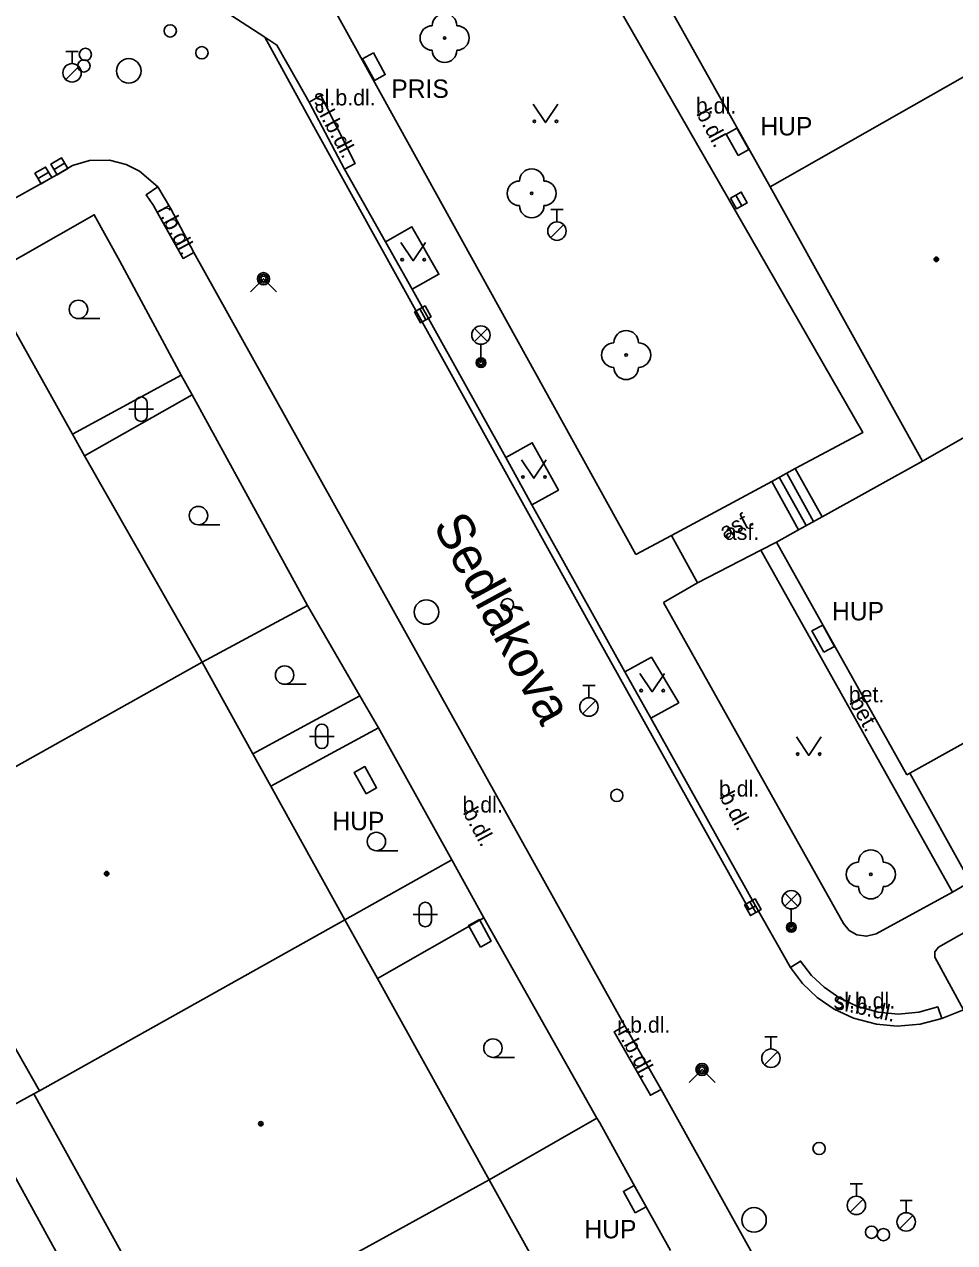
# Model space of a CAD drawing. Extents: x -600391 to -599491, y -1160176 to -1159402.
# Drawn here: x -600270.74 to -600232.82, y -1159878.4 to -1159828.77 of the extents above; entities that cross this region are included whole.
import ezdxf

# ---------------------------------------------------------------- set-up
doc = ezdxf.new("R2010")
doc.units = 0
for name, color, linetype in [('Level 10', 7, 'Continuous'), ('Level 11', 7, 'Continuous'), ('Level 22', 7, 'Continuous'), ('Level 24', 7, 'Continuous'), ('Level 27', 7, 'Continuous'), ('Level 28', 7, 'Continuous'), ('Level 31', 7, 'Continuous'), ('Level 33', 7, 'Continuous'), ('Level 36', 7, 'Continuous'), ('Level 39', 7, 'Continuous'), ('Level 40', 7, 'Continuous'), ('Level 41', 7, 'Continuous'), ('Level 5', 7, 'Continuous'), ('Level 50', 7, 'Continuous'), ('Level 51', 7, 'Continuous'), ('Level 7', 7, 'Continuous'), ('Level 8', 7, 'Continuous')]:
    doc.layers.add(name, color=color, linetype=linetype)

msp = doc.modelspace()

# ---------------------------------------------------------------- linework, layer by layer
at = {"layer": 'Level 10'}
for points in [[(-600266.56, -1159825.53), (-600265.79, -1159826.14), (-600260.94, -1159829.28)], [(-600260.94, -1159829.28), (-600260.44, -1159829.61), (-600259.6, -1159831.09), (-600259.13, -1159831.94)], [(-600259.13, -1159831.94), (-600257.69, -1159834.67)], [(-600269.41, -1159834.89), (-600268.78, -1159834.51), (-600268.08, -1159834.31), (-600267.27, -1159834.3), (-600266.59, -1159834.48), (-600266.04, -1159834.75), (-600265.3, -1159835.39)], [(-600368.24, -1159889.98), (-600352.5, -1159881.19), (-600321.09, -1159863.73), (-600299.81, -1159851.87), (-600276.88, -1159839.05), (-600269.41, -1159834.89)], [(-600257.69, -1159834.67), (-600256.02, -1159837.63)], [(-600263.83, -1159838.06), (-600264.78, -1159836.25), (-600265.3, -1159835.39)], [(-600246.27, -1159869.57), (-600263.83, -1159838.06)], [(-600256.02, -1159837.63), (-600254.93, -1159839.56)], [(-600254.93, -1159839.56), (-600251.12, -1159846.41)], [(-600251.12, -1159846.41), (-600250.05, -1159848.34)], [(-600250.05, -1159848.34), (-600246.26, -1159855.15)], [(-600246.26, -1159855.15), (-600245.2, -1159857.04)], [(-600245.2, -1159857.04), (-600240.94, -1159864.68)], [(-600240.94, -1159864.68), (-600239.52, -1159867.2)], [(-600233.34, -1159869.27), (-600234.23, -1159869.51), (-600235.17, -1159869.58), (-600236.01, -1159869.5), (-600236.94, -1159869.26), (-600237.74, -1159868.89), (-600238.43, -1159868.41), (-600239.02, -1159867.85), (-600239.52, -1159867.2)], [(-600233.34, -1159869.27), (-600232.46, -1159868.92)], [(-600244.78, -1159872.16), (-600246.27, -1159869.57)], [(-600220.17, -1159916.28), (-600233.36, -1159892.71), (-600244.78, -1159872.16)]]:
    msp.add_lwpolyline(points, dxfattribs=at)
at = {"layer": 'Level 11'}
for points in [[(-600239.32, -1159846.86), (-600236.57, -1159845.4), (-600252.37, -1159817.9)], [(-600240.94, -1159864.68), (-600241.2, -1159864.83), (-600247.35, -1159853.81), (-600254.65, -1159840.67), (-600258.86, -1159833.07), (-600260.94, -1159829.28)], [(-600257.69, -1159834.67), (-600257.25, -1159834.43), (-600258.65, -1159831.67), (-600259.13, -1159831.94)], [(-600263.83, -1159838.06), (-600264.27, -1159838.3), (-600265.24, -1159836.56), (-600265.47, -1159836.15), (-600265.77, -1159835.71), (-600265.3, -1159835.39)], [(-600256.02, -1159837.63), (-600254.94, -1159837.02), (-600253.84, -1159838.95), (-600254.93, -1159839.56)], [(-600268.78, -1159845.46), (-600264.34, -1159843.06)], [(-600268.28, -1159846.34), (-600263.89, -1159843.86)], [(-600251.12, -1159846.41), (-600250.04, -1159845.81), (-600248.97, -1159847.74), (-600250.05, -1159848.34)], [(-600240.28, -1159847.39), (-600239.32, -1159846.86)], [(-600239.32, -1159846.86), (-600238.23, -1159848.83)], [(-600244.36, -1159849.59), (-600240.28, -1159847.39)], [(-600240.28, -1159847.39), (-600239.19, -1159849.36)], [(-600239.97, -1159847.22), (-600238.88, -1159849.19)], [(-600239.67, -1159847.05), (-600238.57, -1159849.02)], [(-600245.82, -1159850.37), (-600244.36, -1159849.59)], [(-600244.36, -1159849.59), (-600243.31, -1159851.52)], [(-600240.72, -1159850.19), (-600240.09, -1159849.86)], [(-600243.31, -1159851.52), (-600240.72, -1159850.19)], [(-600232.91, -1159864.12), (-600240.72, -1159850.19)], [(-600244.69, -1159852.32), (-600243.31, -1159851.52)], [(-600244.69, -1159852.32), (-600237.35, -1159865.4)], [(-600246.26, -1159855.15), (-600245.18, -1159854.55), (-600244.07, -1159856.41), (-600245.2, -1159857.04)], [(-600261.42, -1159858.49), (-600257.06, -1159856.13)], [(-600260.69, -1159859.8), (-600256.31, -1159857.43)], [(-600232.91, -1159864.12), (-600232.19, -1159863.71)], [(-600237.35, -1159865.4), (-600237.12, -1159865.68), (-600236.81, -1159865.86), (-600236.41, -1159865.92), (-600236.02, -1159865.82), (-600232.91, -1159864.12)], [(-600232.46, -1159868.92), (-600233.63, -1159866.78), (-600233.63, -1159866.55), (-600233.48, -1159866.36), (-600230.72, -1159864.8)], [(-600256.34, -1159867.64), (-600252.01, -1159865.17)], [(-600239.52, -1159867.2), (-600239.1, -1159866.93), (-600238.66, -1159867.52), (-600238.14, -1159868), (-600237.51, -1159868.45), (-600236.81, -1159868.77), (-600235.94, -1159869.01), (-600235.12, -1159869.09), (-600234.28, -1159869.01), (-600233.51, -1159868.8), (-600233.34, -1159869.27)], [(-600246.27, -1159869.57), (-600246.7, -1159869.82), (-600245.22, -1159872.4), (-600244.78, -1159872.16)]]:
    msp.add_lwpolyline(points, dxfattribs=at)
at = {"layer": 'Level 22'}
for centre in [(-600253.61, -1159829.32), (-600250.06, -1159835.65), (-600246.21, -1159842.24), (-600236.24, -1159863.4)]:
    msp.add_circle(centre, 0.05, dxfattribs=at)
for centre, start, end in [((-600253.61, -1159828.82), 0, 180), ((-600254.11, -1159829.32), 90, 270), ((-600253.11, -1159829.32), 270, 90), ((-600253.61, -1159829.82), 180, 0), ((-600250.06, -1159835.15), 0, 180), ((-600250.56, -1159835.65), 90, 270), ((-600249.56, -1159835.65), 270, 90), ((-600250.06, -1159836.15), 180, 0), ((-600246.21, -1159841.74), 0, 180), ((-600246.71, -1159842.24), 90, 270), ((-600245.71, -1159842.24), 270, 90), ((-600246.21, -1159842.74), 180, 0), ((-600236.24, -1159862.9), 0, 180), ((-600236.74, -1159863.4), 90, 270), ((-600235.74, -1159863.4), 270, 90), ((-600236.24, -1159863.9), 180, 0)]:
    msp.add_arc(centre, 0.5, start, end, dxfattribs=at)
at = {"layer": 'Level 24'}
msp.add_lwpolyline([(-600256.949, -1159830.17), (-600256.471, -1159831.049), (-600256.031, -1159830.81), (-600256.509, -1159829.931)], close=True, dxfattribs=at)
for points in [[(-600241.65, -1159834.11), (-600242.14, -1159833.24), (-600241.7, -1159833), (-600241.21, -1159833.87), (-600241.65, -1159834.11)], [(-600238.15, -1159854.35), (-600238.64, -1159853.48), (-600238.2, -1159853.24), (-600237.72, -1159854.11), (-600238.15, -1159854.35)], [(-600256.81, -1159860.12), (-600257.3, -1159859.25), (-600256.86, -1159859.01), (-600256.38, -1159859.88), (-600256.81, -1159860.12)], [(-600252.15, -1159866.36), (-600252.63, -1159865.48), (-600252.19, -1159865.24), (-600251.71, -1159866.12), (-600252.15, -1159866.36)], [(-600245.84, -1159877.19), (-600246.32, -1159876.32), (-600245.88, -1159876.08), (-600245.4, -1159876.95), (-600245.84, -1159877.19)]]:
    msp.add_lwpolyline(points, dxfattribs=at)
at = {"layer": 'Level 27'}
for p, q in [((-600269.526, -1159834.676), (-600269.094, -1159834.424)), ((-600270.176, -1159835.046), (-600269.744, -1159834.794)), ((-600241.74, -1159835.721), (-600241.5, -1159836.159)), ((-600254.622, -1159840.362), (-600254.378, -1159840.798)), ((-600241.172, -1159864.522), (-600240.928, -1159864.958))]:
    msp.add_line(p, q, dxfattribs=at)
for points in [[(-600270.05, -1159835.262), (-600269.618, -1159835.01), (-600269.87, -1159834.578), (-600270.302, -1159834.83)], [(-600269.4, -1159834.892), (-600268.968, -1159834.64), (-600269.22, -1159834.208), (-600269.652, -1159834.46)], [(-600241.959, -1159835.841), (-600241.719, -1159836.279), (-600241.281, -1159836.039), (-600241.521, -1159835.601)], [(-600254.84, -1159840.483), (-600254.597, -1159840.92), (-600254.16, -1159840.677), (-600254.403, -1159840.24)], [(-600241.39, -1159864.643), (-600241.147, -1159865.08), (-600240.71, -1159864.837), (-600240.953, -1159864.4)]]:
    msp.add_lwpolyline(points, close=True, dxfattribs=at)
for centre in [(-600266.48, -1159830.66), (-600254.35, -1159852.71), (-600241, -1159877.48)]:
    msp.add_circle(centre, 0.5, dxfattribs=at)
at = {"layer": 'Level 28'}
for p, q in [((-600269.04, -1159829.865), (-600268.54, -1159829.865)), ((-600268.79, -1159830.365), (-600268.79, -1159829.865)), ((-600269.048, -1159831.012), (-600268.518, -1159830.482)), ((-600249.28, -1159836.315), (-600248.78, -1159836.315)), ((-600249.03, -1159836.815), (-600249.03, -1159836.315)), ((-600249.288, -1159837.462), (-600248.758, -1159836.932)), ((-600247.98, -1159855.705), (-600247.48, -1159855.705)), ((-600247.73, -1159856.205), (-600247.73, -1159855.705)), ((-600247.988, -1159856.852), (-600247.458, -1159856.322)), ((-600240.56, -1159870.015), (-600240.06, -1159870.015)), ((-600240.31, -1159870.515), (-600240.31, -1159870.015)), ((-600240.568, -1159871.162), (-600240.038, -1159870.632)), ((-600237.08, -1159876.015), (-600236.58, -1159876.015)), ((-600236.83, -1159876.515), (-600236.83, -1159876.015)), ((-600237.088, -1159877.162), (-600236.558, -1159876.632)), ((-600235.05, -1159876.685), (-600234.55, -1159876.685)), ((-600234.8, -1159877.185), (-600234.8, -1159876.685)), ((-600235.058, -1159877.832), (-600234.528, -1159877.302))]:
    msp.add_line(p, q, dxfattribs=at)
for centre, radius in [((-600264.79, -1159829.03), 0.25), ((-600268.25, -1159829.99), 0.25), ((-600263.5, -1159829.92), 0.25), ((-600268.79, -1159830.74), 0.375), ((-600268.31, -1159830.46), 0.25), ((-600249.03, -1159837.19), 0.375), ((-600251.05, -1159852.41), 0.25), ((-600247.73, -1159856.58), 0.375), ((-600246.59, -1159860.18), 0.25), ((-600240.31, -1159870.89), 0.375), ((-600238.35, -1159874.57), 0.25), ((-600236.83, -1159876.89), 0.375), ((-600234.8, -1159877.56), 0.375), ((-600236.21, -1159877.98), 0.25), ((-600235.73, -1159878.08), 0.25)]:
    msp.add_circle(centre, radius, dxfattribs=at)
at = {"layer": 'Level 31'}
for points in [[(-600261.52, -1159839.66), (-600260.99, -1159839.13), (-600260.46, -1159839.66)], [(-600243.65, -1159871.88), (-600243.12, -1159871.35), (-600242.59, -1159871.88)]]:
    msp.add_lwpolyline(points, dxfattribs=at)
for centre, radius in [((-600260.99, -1159839.13), 0.25), ((-600260.99, -1159839.13), 0.18), ((-600260.99, -1159839.13), 0.11), ((-600243.12, -1159871.35), 0.25), ((-600243.12, -1159871.35), 0.18), ((-600243.12, -1159871.35), 0.11)]:
    msp.add_circle(centre, radius, dxfattribs=at)
at = {"layer": 'Level 33'}
for p, q in [((-600252.395, -1159841.69), (-600251.865, -1159841.16)), ((-600252.395, -1159841.16), (-600251.865, -1159841.69)), ((-600252.13, -1159841.8), (-600252.13, -1159842.55)), ((-600239.745, -1159864.7), (-600239.215, -1159864.17)), ((-600239.745, -1159864.17), (-600239.215, -1159864.7)), ((-600239.48, -1159864.81), (-600239.48, -1159865.56))]:
    msp.add_line(p, q, dxfattribs=at)
for centre, radius in [((-600252.13, -1159841.425), 0.375), ((-600252.13, -1159842.55), 0.2), ((-600252.13, -1159842.55), 0.145), ((-600252.13, -1159842.55), 0.0876), ((-600239.48, -1159864.435), 0.375), ((-600239.48, -1159865.56), 0.2), ((-600239.48, -1159865.56), 0.145), ((-600239.48, -1159865.56), 0.0876)]:
    msp.add_circle(centre, radius, dxfattribs=at)
at = {"layer": 'Level 36'}
for p, q in [((-600268.53, -1159840.755), (-600267.655, -1159840.755)), ((-600266.476, -1159844.446), (-600265.476, -1159844.446)), ((-600266.226, -1159844.196), (-600266.226, -1159844.696)), ((-600265.726, -1159844.196), (-600265.726, -1159844.696)), ((-600263.64, -1159849.155), (-600262.765, -1159849.155)), ((-600260.13, -1159855.655), (-600259.255, -1159855.655)), ((-600259.116, -1159857.776), (-600258.116, -1159857.776)), ((-600258.866, -1159857.526), (-600258.866, -1159858.026)), ((-600258.366, -1159857.526), (-600258.366, -1159858.026)), ((-600256.39, -1159862.435), (-600255.515, -1159862.435)), ((-600254.646, -1159864.786), (-600254.646, -1159865.286)), ((-600254.146, -1159864.786), (-600254.146, -1159865.286)), ((-600254.896, -1159865.036), (-600253.896, -1159865.036)), ((-600251.64, -1159870.855), (-600250.765, -1159870.855))]:
    msp.add_line(p, q, dxfattribs=at)
for points in [[(-600250, -1159832.02), (-600249.5, -1159832.77), (-600249, -1159832.02)], [(-600255.39, -1159837.65), (-600254.89, -1159838.4), (-600254.39, -1159837.65)], [(-600250.47, -1159846.51), (-600249.97, -1159847.26), (-600249.47, -1159846.51)], [(-600245.65, -1159855.21), (-600245.15, -1159855.96), (-600244.65, -1159855.21)], [(-600239.27, -1159857.8), (-600238.77, -1159858.55), (-600238.27, -1159857.8)]]:
    msp.add_lwpolyline(points, dxfattribs=at)
for centre, radius in [((-600249.95, -1159832.72), 0.05), ((-600249.051, -1159832.72), 0.05), ((-600255.34, -1159838.35), 0.05), ((-600254.441, -1159838.35), 0.05), ((-600268.53, -1159840.38), 0.375), ((-600250.42, -1159847.21), 0.05), ((-600249.521, -1159847.21), 0.05), ((-600263.64, -1159848.78), 0.375), ((-600260.13, -1159855.28), 0.375), ((-600245.6, -1159855.91), 0.05), ((-600244.701, -1159855.91), 0.05), ((-600239.22, -1159858.5), 0.05), ((-600238.321, -1159858.5), 0.05), ((-600256.39, -1159862.06), 0.375), ((-600251.64, -1159870.48), 0.375)]:
    msp.add_circle(centre, radius, dxfattribs=at)
for centre, start, end in [((-600265.976, -1159844.196), 0, 180), ((-600265.976, -1159844.696), 180, 0), ((-600258.616, -1159857.526), 0, 180), ((-600258.616, -1159858.026), 180, 0), ((-600254.396, -1159864.786), 0, 180), ((-600254.396, -1159865.286), 180, 0)]:
    msp.add_arc(centre, 0.25, start, end, dxfattribs=at)
at = {"layer": 'Level 39'}
for centre, radius in [((-600233.57, -1159838.34), 0.09), ((-600233.57, -1159838.34), 0.0398), ((-600267.38, -1159863.37), 0.09), ((-600267.38, -1159863.37), 0.0398), ((-600261.1, -1159873.56), 0.09), ((-600261.1, -1159873.56), 0.0398)]:
    msp.add_circle(centre, radius, dxfattribs=at)
at = {"layer": 'Level 5'}
for points in [[(-600240.34, -1159835.38), (-600248.62, -1159820.62)], [(-600231.22, -1159830.2), (-600240.34, -1159835.38)], [(-600234.14, -1159846.56), (-600240.34, -1159835.38)], [(-600272.36, -1159839.07), (-600268.78, -1159845.46)], [(-600227.68, -1159842.88), (-600234.14, -1159846.56)], [(-600268.78, -1159845.46), (-600268.28, -1159846.34)], [(-600268.28, -1159846.34), (-600263.49, -1159854.75)], [(-600238.23, -1159848.83), (-600234.14, -1159846.56)], [(-600239.19, -1159849.36), (-600238.23, -1159848.83)], [(-600240.09, -1159849.86), (-600239.19, -1159849.36)], [(-600234.77, -1159859.35), (-600240.09, -1159849.86)], [(-600263.49, -1159854.75), (-600275.48, -1159861.46)], [(-600263.49, -1159854.75), (-600261.42, -1159858.49)], [(-600230.3, -1159856.86), (-600234.65, -1159859.28)], [(-600261.42, -1159858.49), (-600260.69, -1159859.8)], [(-600234.65, -1159859.28), (-600234.77, -1159859.35)], [(-600232.19, -1159863.71), (-600234.65, -1159859.28)], [(-600260.69, -1159859.8), (-600257.67, -1159865.25)], [(-600270.12, -1159872.22), (-600276.06, -1159861.79)], [(-600257.67, -1159865.25), (-600270.12, -1159872.22)], [(-600257.67, -1159865.25), (-600256.34, -1159867.64)], [(-600256.34, -1159867.64), (-600251.8, -1159875.84)], [(-600270.35, -1159872.34), (-600270.12, -1159872.22)], [(-600264.54, -1159882.86), (-600270.35, -1159872.34)], [(-600251.8, -1159875.84), (-600264.54, -1159882.86)], [(-600251.8, -1159875.84), (-600248.85, -1159881.15)]]:
    msp.add_lwpolyline(points, dxfattribs=at)
at = {"layer": 'Level 51'}
for points in [[(-600270.35, -1159872.34), (-600272.38, -1159873.45)], [(-600271.67, -1159874.72), (-600266.6, -1159883.96)]]:
    msp.add_lwpolyline(points, dxfattribs=at)
at = {"layer": 'Level 7'}
for points in [[(-600245.82, -1159850.37), (-600261.04, -1159822.84)], [(-600272.36, -1159839.07), (-600267.89, -1159836.52), (-600266.84, -1159838.42), (-600264.34, -1159843.06)], [(-600263.89, -1159843.86), (-600259.2, -1159852.44)], [(-600259.2, -1159852.44), (-600263.49, -1159854.75)], [(-600259.2, -1159852.44), (-600257.06, -1159856.13)], [(-600256.31, -1159857.43), (-600253.32, -1159862.81)], [(-600253.32, -1159862.81), (-600257.67, -1159865.25)], [(-600252.01, -1159865.17), (-600247.4, -1159873.33)], [(-600247.4, -1159873.33), (-600251.8, -1159875.84)], [(-600247.4, -1159873.33), (-600247.29, -1159873.52)], [(-600245.92, -1159876), (-600244.41, -1159878.73)]]:
    msp.add_lwpolyline(points, dxfattribs=at)
at = {"layer": 'Level 8'}
for points in [[(-600263.89, -1159843.86), (-600264.34, -1159843.06)], [(-600256.31, -1159857.43), (-600257.06, -1159856.13)], [(-600252.01, -1159865.17), (-600253.32, -1159862.81)], [(-600245.92, -1159876), (-600247.29, -1159873.52)]]:
    msp.add_lwpolyline(points, dxfattribs=at)

# ---------------------------------------------------------------- texts
at = {"layer": 'Level 40'}
for s, p in [('sl.b.dl.', (-600258.93, -1159832.07)), ('b.dl.', (-600243.37, -1159832.4)), ('asf.', (-600242.19, -1159849.77)), ('bet.', (-600237.14, -1159856.39)), ('b.dl.', (-600242.43, -1159860.23)), ('b.dl.', (-600252.88, -1159860.88)), ('sl.b.dl.', (-600237.76, -1159868.87)), ('r.b.dl.', (-600246.58, -1159869.85))]:
    msp.add_text(s, height=0.65, dxfattribs=at).set_placement(p)
for s, rotation, p in [('sl.b.dl.', 298.28, (-600258.93, -1159832.07)), ('b.dl.', 298.28, (-600243.37, -1159832.4)), ('r.b.dl.', 298.28, (-600265.34, -1159836.32)), ('asf.', 27.56, (-600242.19, -1159849.77)), ('bet.', 299.56, (-600237.14, -1159856.39)), ('b.dl.', 298.28, (-600242.43, -1159860.23)), ('b.dl.', 298.28, (-600252.88, -1159860.88)), ('sl.b.dl.', 347.42, (-600237.76, -1159868.87)), ('r.b.dl.', 298.28, (-600246.58, -1159869.85))]:
    msp.add_text(s, height=0.65, rotation=rotation, dxfattribs=at).set_placement(p)
at = {"layer": 'Level 41'}
for s, p in [('PRIS', (-600255.78, -1159831.76)), ('PRIS', (-600255.78, -1159831.76)), ('HUP', (-600240.74, -1159833.29)), ('HUP', (-600240.74, -1159833.29)), ('HUP', (-600237.82, -1159853.05)), ('HUP', (-600237.82, -1159853.05)), ('HUP', (-600258.18, -1159861.6)), ('HUP', (-600258.18, -1159861.6)), ('HUP', (-600247.91, -1159878.23)), ('HUP', (-600247.91, -1159878.23))]:
    msp.add_text(s, height=0.75, dxfattribs=at).set_placement(p)
at = {"layer": 'Level 50'}
msp.add_text('Sedlákova', height=1.5, rotation=298.4605, dxfattribs=at).set_placement((-600254.101, -1159849.184))

doc.saveas('drawing.dxf')
